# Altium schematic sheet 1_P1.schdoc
size 848 x 601 mm; Symbol: Drawing-Symbol_A4; Device: Drawing-Symbol_A4; Company: 嘉立创EDA; Version: V1.0; Page Size: A4; @Project Name: New Project; @Page Count: 1; @Update Date: 2025-11-15; @Create Date: 2025-05-18; @Schematic Name: Schematic1; @Page No: 1; @Page Name: P1; @Create Time: 04:48:49; @Update Time: 13:35:40; Width: 3304; Height: 2338; Region Start: 1; X Region Count: 6; Y Region Count: 4; Blade Width: 10; Title Block Position: 3; @Board Name: Board1
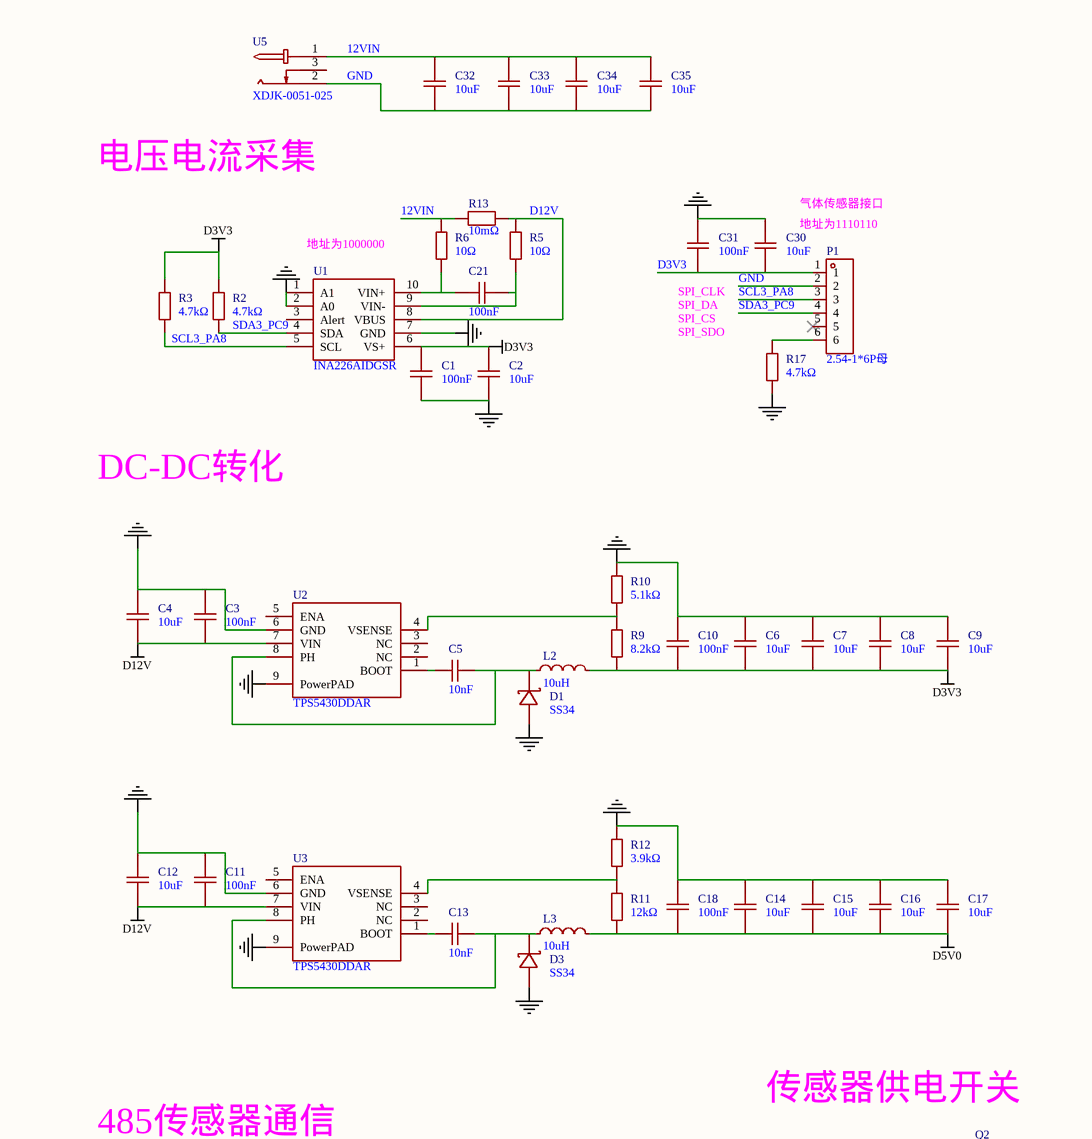
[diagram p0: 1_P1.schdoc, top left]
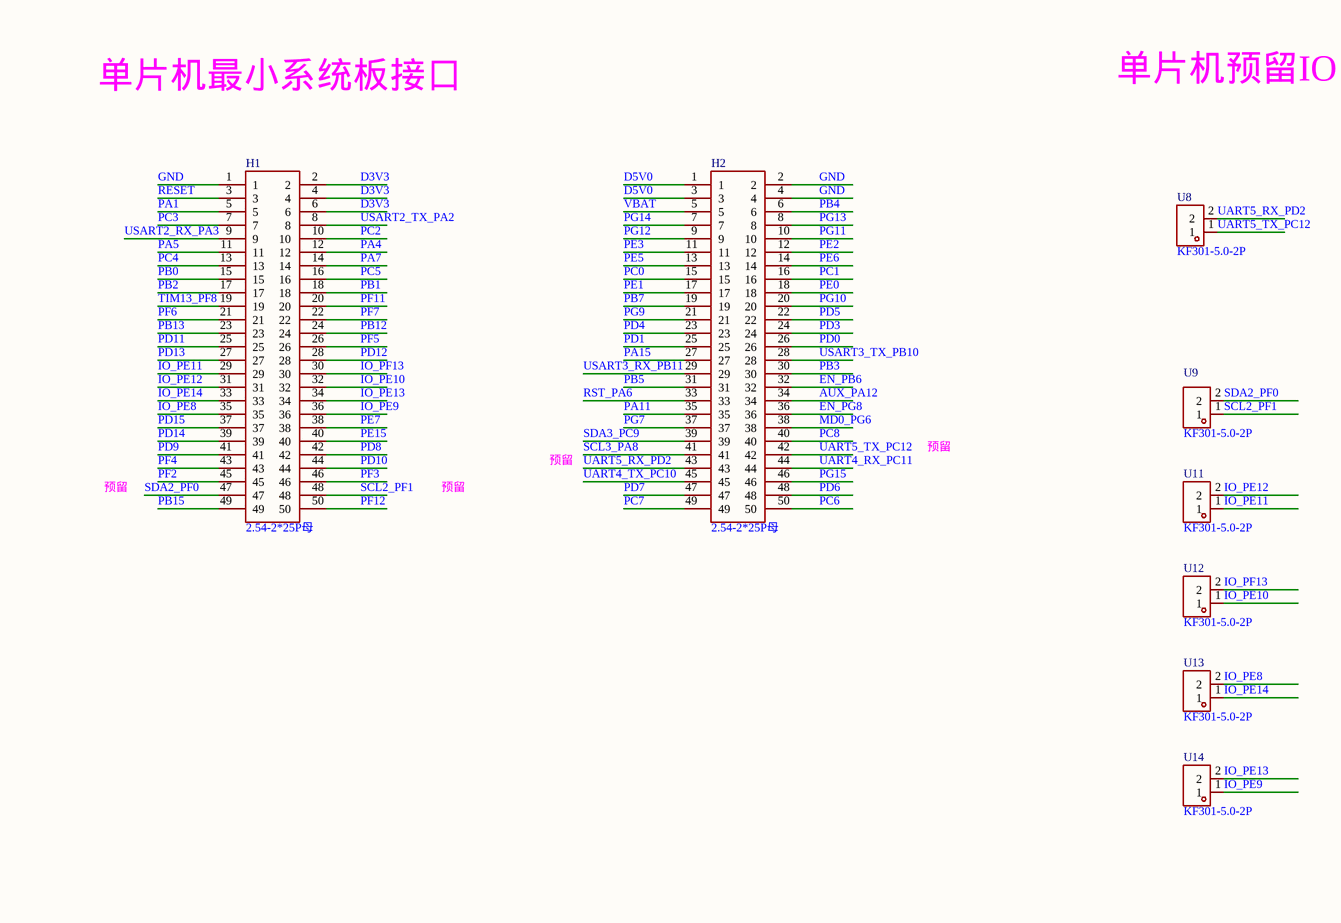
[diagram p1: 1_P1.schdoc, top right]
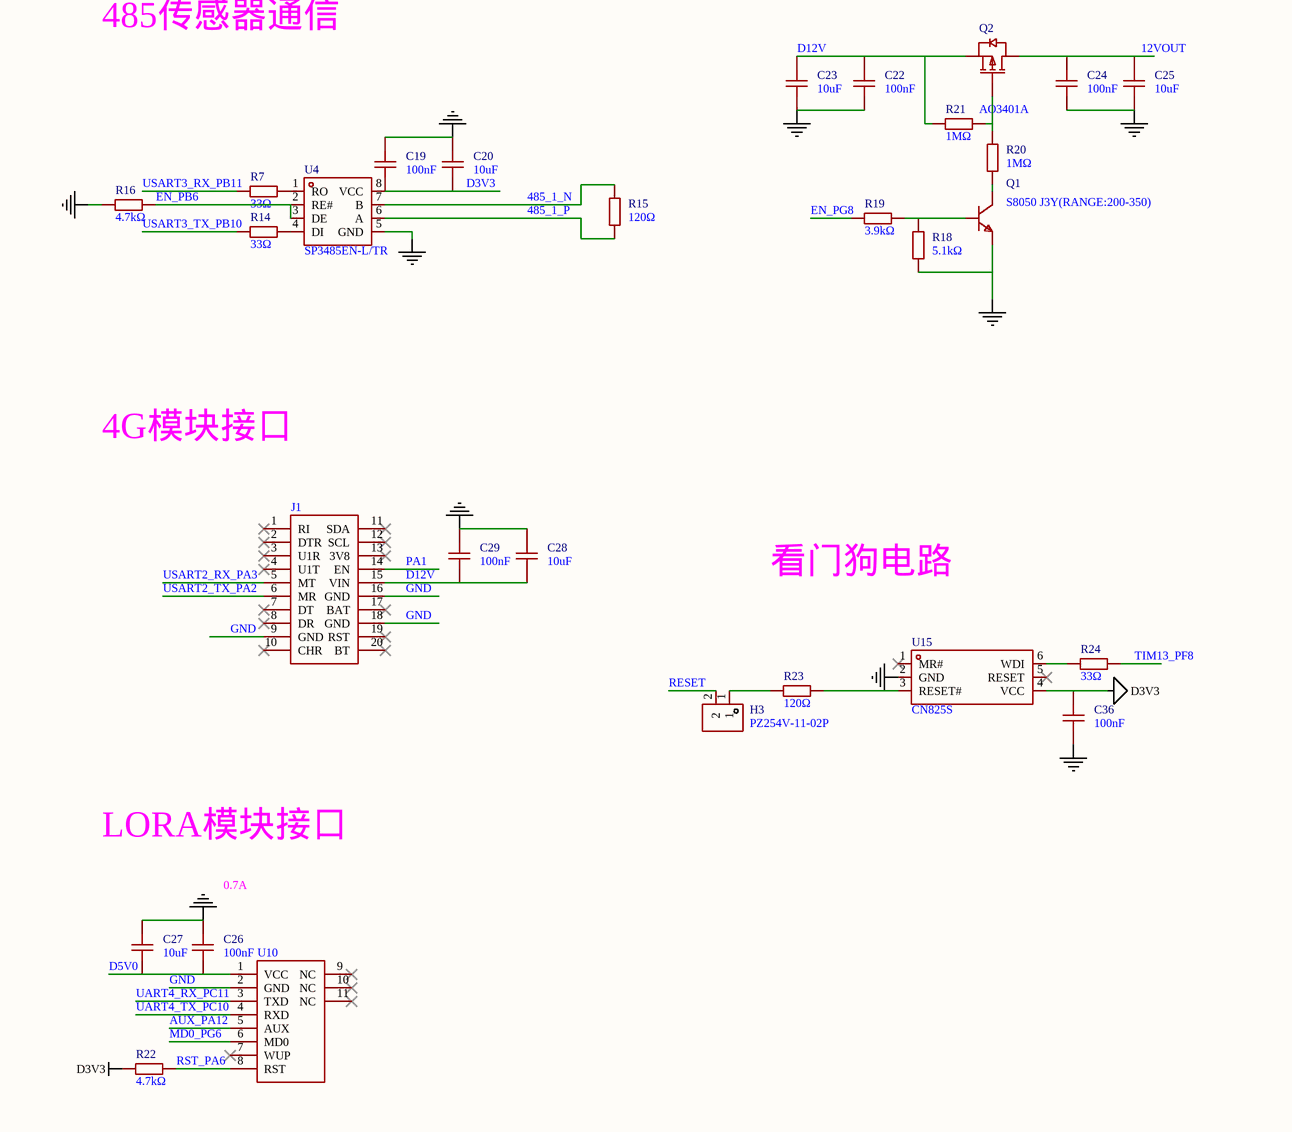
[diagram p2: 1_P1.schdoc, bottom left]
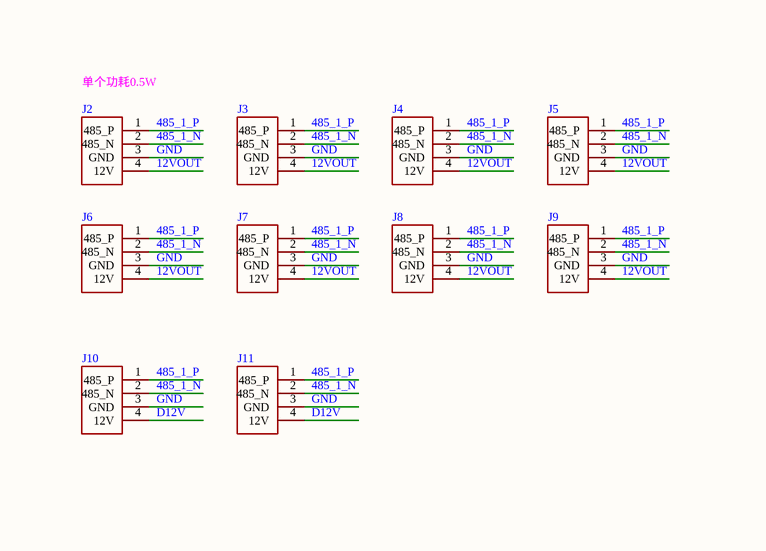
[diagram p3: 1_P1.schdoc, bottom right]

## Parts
C1  100nF  [C0603]
C2  10uF  [C0805]
C3  100nF  [C0603]
C4  10uF  [C0805]
C5  10nF  [C0603]
C6  10uF  [C0805]
C7  10uF  [C0805]
C8  10uF  [C0805]
C9  10uF  [C0805]
C10  100nF  [C0603]
C11  100nF  [C0603]
C12  10uF  [C0805]
C13  10nF  [C0603]
C14  10uF  [C0805]
C15  10uF  [C0805]
C16  10uF  [C0805]
C17  10uF  [C0805]
C18  100nF  [C0603]
C19  100nF  [C0603]
C20  10uF  [C0805]
C21  100nF  [C0603]
C22  100nF  [C0603]
C23  10uF  [C0805]
C24  100nF  [C0603]
C25  10uF  [C0805]
C26  100nF  [C0603]
C27  10uF  [C0805]
C28  10uF  [C0805]
C29  100nF  [C0603]
C30  10uF  [C0805]
C31  100nF  [C0603]
C32  10uF  [C0805]
C33  10uF  [C0805]
C34  10uF  [C0805]
C35  10uF  [C0805]
C36  100nF  [C0603]
D1  SS34  [SMA_L4.3-W2.6-LS5.2-RD]
D3  SS34  [SMA_L4.3-W2.6-LS5.2-RD]
H1  2.54-2*25P母  [HDR-TH_50P-P2.54-V-F-R2-C25-S2.54-1]
H2  2.54-2*25P母  [HDR-TH_50P-P2.54-V-F-R2-C25-S2.54-1]
H3  PZ254V-11-02P  [HDR-TH_2P-P2.54-V-M]
J1  (no value)  [HDR-TH_20P-P2.54-V-M-R2-C10-S2.54_HIF3H-20P-2.54W]
J2  (no value)  [CONN-TH_4P-P5.00_KF301-5.0-4P]
J3  (no value)  [CONN-TH_4P-P5.00_KF301-5.0-4P]
J4  (no value)  [CONN-TH_4P-P5.00_KF301-5.0-4P]
J5  (no value)  [CONN-TH_4P-P5.00_KF301-5.0-4P]
J6  (no value)  [CONN-TH_4P-P5.00_KF301-5.0-4P]
J7  (no value)  [CONN-TH_4P-P5.00_KF301-5.0-4P]
J8  (no value)  [CONN-TH_4P-P5.00_KF301-5.0-4P]
J9  (no value)  [CONN-TH_4P-P5.00_KF301-5.0-4P]
J10  (no value)  [CONN-TH_4P-P5.00_KF301-5.0-4P]
J11  (no value)  [CONN-TH_4P-P5.00_KF301-5.0-4P]
L2  10uH  [IND-SMD_L7.1-W6.6]
L3  10uH  [IND-SMD_L7.1-W6.6]
P1  2.54-1*6P母  [HDR-TH_6P-P2.54-V-F]
Q1  S8050 J3Y(RANGE:200-350)  [SOT-23-3_L3.0-W1.7-P0.95-LS2.9-BR]
Q2  AO3401A  [SOT-23_L2.9-W1.3-P1.90-LS2.4-BR]
R2  4.7kΩ  [R0603]
R3  4.7kΩ  [R0603]
R5  10Ω  [R0603]
R6  10Ω  [R0603]
R7  33Ω  [R0603]
R9  8.2kΩ  [R0603]
R10  5.1kΩ  [R0603]
R11  12kΩ  [R0603]
R12  3.9kΩ  [R0603]
R13  10mΩ  [R2512]
R14  33Ω  [R0603]
R15  120Ω  [R0603]
R16  4.7kΩ  [R0603]
R17  4.7kΩ  [R0603]
R18  5.1kΩ  [R0603]
R19  3.9kΩ  [R0603]
R20  1MΩ  [R0603]
R21  1MΩ  [R0603]
R22  4.7kΩ  [R0603]
R23  120Ω  [R0603]
R24  33Ω  [R0603]
U1  INA226AIDGSR  [MSOP-10_L3.0-W3.0-P0.50-LS5.0-BL]
U2  TPS5430DDAR  [ESOP-8_L4.9-W3.9-P1.27-LS6.0-TL-EP]
U3  TPS5430DDAR  [ESOP-8_L4.9-W3.9-P1.27-LS6.0-TL-EP]
U4  SP3485EN-L/TR  [SOIC-8_L5.0-W4.0-P1.27-LS6.0-BL]
U5  XDJK-0051-025  [DC-IN-TH_XDJK-0051-025]
U8  KF301-5.0-2P  [CONN-TH_P5.00_KF301-5.0-2P]
U9  KF301-5.0-2P  [CONN-TH_P5.00_KF301-5.0-2P]
U10  (no value)  [LORA]
U11  KF301-5.0-2P  [CONN-TH_P5.00_KF301-5.0-2P]
U12  KF301-5.0-2P  [CONN-TH_P5.00_KF301-5.0-2P]
U13  KF301-5.0-2P  [CONN-TH_P5.00_KF301-5.0-2P]
U14  KF301-5.0-2P  [CONN-TH_P5.00_KF301-5.0-2P]
U15  CN825S  [SOT-23-6_L2.9-W1.6-P0.95-LS2.8-BL]

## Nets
D3V3: C1.2 C2.2 C6.1 C7.1 C8.1 C9.1 C10.2 C19.2 C20.2 C30.2 C31.2 C36.2 H1.2 H1.4 H1.6 L2.2 P1.1 R2.2 R3.2 R9.1 R22.2 U1.6(VS+) U4.8(VCC) U15.4(VCC)
D5V0: C14.1 C15.1 C16.1 C17.1 C18.2 C26.2 C27.2 H2.1 H2.3 L3.2 R11.1 U10.1(VCC)
D12V: C3.2 C4.2 C11.2 C12.2 C22.1 C23.1 C28.2 C29.2 J1.15(VIN) J10.4(12V) J11.4(12V) Q2.2(S) R5.2 R13.2 R21.2 U1.8(VBUS) U2.7(VIN) U3.7(VIN)
GND: C1.1 C2.1 C3.1 C4.1 C6.2 C7.2 C8.2 C9.2 C10.1 C11.1 C12.1 C14.2 C15.2 C16.2 C17.2 C18.1 C19.1 C20.1 C22.2 C23.2 C24.2 C25.2 C26.1 C27.1 C28.1 C29.1 C30.1 C31.1 C32.2 C33.2 C34.2 C35.2 C36.1 D1.2(A) D3.2(A) H1.1 H2.2 H2.4 J1.9(GND) J1.16(GND) J1.18(GND) J2.3(GND) J3.3(GND) J4.3(GND) J5.3(GND) J6.3(GND) J7.3(GND) J8.3(GND) J9.3(GND) J10.3(GND) J11.3(GND) P1.2 Q1.2(E) R10.2 R12.2 R16.1 R17.1 R18.1 U1.1(A1) U1.2(A0) U1.7(GND) U2.6(GND) U2.9(PowerPAD) U3.6(GND) U3.9(PowerPAD) U4.5(GND) U5.2 U10.2(GND) U15.2(GND)
12VIN: C32.1 C33.1 C34.1 C35.1 R6.2 R13.1 U5.1
12VOUT: C24.1 C25.1 J2.4(12V) J3.4(12V) J4.4(12V) J5.4(12V) J6.4(12V) J7.4(12V) J8.4(12V) J9.4(12V) Q2.3(D)
485_1_N: J2.2(485_N) J3.2(485_N) J4.2(485_N) J5.2(485_N) J6.2(485_N) J7.2(485_N) J8.2(485_N) J9.2(485_N) J10.2(485_N) J11.2(485_N) R15.2 U4.7(B)
485_1_P: J2.1(485_P) J3.1(485_P) J4.1(485_P) J5.1(485_P) J6.1(485_P) J7.1(485_P) J8.1(485_P) J9.1(485_P) J10.1(485_P) J11.1(485_P) R15.1 U4.6(A)
AUX_PA12: H2.34 U10.5(AUX)
EN_PB6: H2.32 R16.2 U4.2(RE#) U4.3(DE)
EN_PG8: H2.36 R19.2
IO_PE8: H1.35 U13.2
IO_PE9: H1.36 U14.1
IO_PE10: H1.32 U12.1
IO_PE11: H1.29 U11.1
IO_PE12: H1.31 U11.2
IO_PE13: H1.34 U14.2
IO_PE14: H1.33 U13.1
IO_PF13: H1.30 U12.2
MD0_PG6: H2.38 U10.6(MD0)
PA1: H1.5 J1.14(EN)
PA4: H1.12
PA5: H1.11
PA7: H1.14
PA11: H2.35
PA15: H2.27
PB0: H1.15
PB1: H1.18
PB2: H1.17
PB3: H2.30
PB4: H2.6
PB5: H2.31
PB7: H2.19
PB12: H1.24
PB13: H1.23
PB15: H1.49
PC0: H2.15
PC1: H2.16
PC2: H1.10
PC3: H1.7
PC4: H1.13
PC5: H1.16
PC6: H2.50
PC7: H2.49
PC8: H2.40
PD0: H2.26
PD1: H2.25
PD3: H2.24
PD4: H2.23
PD5: H2.22
PD6: H2.48
PD7: H2.47
PD8: H1.42
PD9: H1.41
PD10: H1.44
PD11: H1.25
PD12: H1.28
PD13: H1.27
PD14: H1.39
PD15: H1.37
PE0: H2.18
PE1: H2.17
PE2: H2.12
PE3: H2.11
PE5: H2.13
PE6: H2.14
PE7: H1.38
PE15: H1.40
PF2: H1.45
PF3: H1.46
PF4: H1.43
PF5: H1.26
PF6: H1.21
PF7: H1.22
PF11: H1.20
PF12: H1.50
PG7: H2.37
PG9: H2.21
PG10: H2.20
PG11: H2.10
PG12: H2.9
PG13: H2.8
PG14: H2.7
PG15: H2.46
RESET: H1.3 H3.2
RST_PA6: H2.33 R22.1 U10.8(RST)
SCL2_PF1: H1.48 U9.1
SCL3_PA8: H2.41 P1.3 R3.1 U1.5(SCL)
SDA2_PF0: H1.47 U9.2
SDA3_PC9: H2.39 P1.4 R2.1 U1.4(SDA)
TIM13_PF8: H1.19 R24.2
UART4_RX_PC11: H2.44 U10.3(TXD)
UART4_TX_PC10: H2.45 U10.4(RXD)
UART5_RX_PD2: H2.43 U8.2
UART5_TX_PC12: H2.42 U8.1
USART2_RX_PA3: H1.9 J1.5(MT)
USART2_TX_PA2: H1.8 J1.6(MR)
USART3_RX_PB11: H2.29 R7.1
USART3_TX_PB10: H2.28 R14.1
VBAT: H2.5
NetC5_1: C5.1 D1.1(K) L2.1 U2.8(PH)
NetC5_2: C5.2 U2.1(BOOT)
NetC13_1: C13.1 D3.1(K) L3.1 U3.8(PH)
NetC13_2: C13.2 U3.1(BOOT)
NetC21_1: C21.1 R5.1 U1.9(VIN-)
NetC21_2: C21.2 R6.1 U1.10(VIN+)
NetH3_1: H3.1 R23.2
NetP1_6: P1.6 R17.2
NetQ1_1: Q1.1(B) R18.2 R19.1
NetQ1_3: Q1.3(C) R20.1
NetQ2_1: Q2.1(G) R20.2 R21.1
NetR7_2: R7.2 U4.1(RO)
NetR9_2: R9.2 R10.1 U2.4(VSENSE)
NetR11_2: R11.2 R12.1 U3.4(VSENSE)
NetR14_2: R14.2 U4.4(DI)
NetR23_1: R23.1 U15.3(RESET#)
NetR24_1: R24.1 U15.6(WDI)

Not connected (* = marked no-connect by the designer): J1 1(RI)* 2(DTR)* 3(U1R)* 4(U1T)* 7(DT)* 8(DR)* 10(CHR)* 11(SDA)* 12(SCL)* 13(3V8)* 17(BAT)* 19(RST)* 20(BT)*; P1 5*; U1 3(Alert); U2 2(NC) 3(NC) 5(ENA); U3 2(NC) 3(NC) 5(ENA); U5 3; U10 7(WUP)* 9(NC)* 10(NC)* 11(NC)*; U15 1(MR#)* 5(RESET)*

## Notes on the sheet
- 单片机最小系统板接口
- 单片机预留IO
- 电压电流采集
- 气体传感器接口
- 地址为1110110
- (near U1) 地址为1000000
- (near C31) SPI_CLK
- SPI_CS
- (near C31) SPI_DA
- SPI_SDO
- DC-DC转化
- 预留
- 传感器供电开关
- 485传感器通信
- (near J2) 单个功耗0.5W
- 4G模块接口
- 看门狗电路
- LORA模块接口
- (near C26) 0.7A

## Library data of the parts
C1 C3 C10 C11 C18 C19 C21 C22 C24 C26 C29 C31 C36 = CC0603KRX7R9BB104: Manufacturer: YAGEO(国巨); Add into BOM: yes; Tolerance: ±10%; Voltage Rated: 50V; Temperature Coefficient: X7R
C2 C4 C6-C9 C12 C14-C17 C20 C23 C25 C27 C28 C30 C32-C35 = CL21A106KAYNNNE_C15850: Manufacturer: SAMSUNG(三星); Add into BOM: yes; Tolerance: ±10%; Voltage Rated: 25V; Temperature Coefficient: X5R
C5 C13 = 0603B103K500NT: Manufacturer: FH(风华); Add into BOM: yes; Tolerance: ±10%; Voltage Rating: 50V; Temperature Coefficient: X7R
D1 D3 = SS34_C8678: Manufacturer: MDD(辰达半导体); Add into BOM: yes; Diode Configuration: 独立式; Forward Voltage (Vf@If): 550mV@3A; Reverse Voltage (Vr): 40V; Rectified Current: 3A; Reverse Leakage Current (Ir): 500uA@40V
H1 H2 = 2.54-2*25P母: Manufacturer: BOOMELE(博穆精密); Symbol: 2.54mm 2*25P female header; Add into BOM: yes; Holes Structure: 2x25P; Pitch: 2.54mm; Number of Holes: 50P
H3 = PZ254V-11-02P: Manufacturer: XFCN(兴飞); Add into BOM: yes; Pin Structure: 1x2P; Pitch: 2.54mm; Circluar Pins/Square Pins: 方针
J1 = EC800K核心板: Add into BOM: yes
J2-J11 = 传感器端子: Add into BOM: yes
L2 L3 = MWSA0603S-100MT: Manufacturer: Sunlord(顺络); Symbol: MWSA0603-100MT; Add into BOM: yes; Tolerance: ±20%; Rated Current: 4.5A; Current - Saturation(Isat): 5.5A; DC Resistance(DCR): 67mΩ
P1 = 2.54-1*6P母: Manufacturer: BOOMELE(博穆精密); Symbol: Header-Female-2.54_1x6; Add into BOM: yes; Holes Structure: 1x6P; Pitch: 2.54mm; Number of Holes: 6P
Q1 = S8050 J3Y(RANGE:200-350): Manufacturer: CJ(江苏长电/长晶); Symbol: S8050_C2146; Add into BOM: yes; type: NPN; Current - Collector(Ic): 500mA; Collector - Emitter Voltage VCEO: 25V; Pd - Power Dissipation: 300mW; DC Current Gain: 200@500mA,1V; Transition frequency(fT): 150MHz; Current - Collector Cutoff: 100nA; Vce Saturation(VCE(sat)): 600mV
Q2 = AO3401A_C15127: Manufacturer: AOS; Add into BOM: yes; Type: 1个P沟道; Drain Source Voltage (Vdss): 30V; Continuous Drain Current (Id): 4A; Drain Source On Resistance (RDS(on)@Vgs,Id): 44mΩ@10V,4.3A; Power Dissipation (Pd): 1.4W; Gate Threshold Voltage (Vgs(th)@Id): 1.3V@250uA; Total Gate Charge (Qg@Vgs): 12.2nC@4.5V; Input Capacitance (Ciss@Vds): 1.2nF@15V
R2 R3 R16 R17 R22 = 0603WAF4701T5E: Manufacturer: UNI-ROYAL(厚声); Add into BOM: yes; Tolerance: ±1%; Power(Watts): 100mW; Overload Voltage (Max): 75V; Temperature Coefficient: ±100ppm/℃
R5 R6 = 0603WAF100JT5E: Manufacturer: UNI-ROYAL(厚声); Add into BOM: yes; Tolerance: ±1%; Power(Watts): 100mW; Overload Voltage (Max): 75V; Temperature Coefficient: ±400ppm/℃
R7 R14 R24 = 0603WAF330JT5E: Manufacturer: UNI-ROYAL(厚声); Add into BOM: yes; Tolerance: ±1%; Power(Watts): 100mW; Overload Voltage (Max): 75V; Temperature Coefficient: ±100ppm/℃
R9 = 0603WAF8201T5E: Manufacturer: UNI-ROYAL(厚声); Add into BOM: yes; Tolerance: ±1%; Power(Watts): 100mW; Overload Voltage (Max): 75V; Temperature Coefficient: ±100ppm/℃
R10 R18 = 0603WAF5101T5E: Manufacturer: UNI-ROYAL(厚声); Add into BOM: yes; Tolerance: ±1%; Power(Watts): 100mW; Overload Voltage (Max): 75V; Temperature Coefficient: ±100ppm/℃
R11 = 0603WAF1202T5E: Manufacturer: UNI-ROYAL(厚声); Add into BOM: yes; Tolerance: ±1%; Power(Watts): 100mW; Overload Voltage (Max): 75V; Temperature Coefficient: ±100ppm/℃
R12 R19 = 0603WAF3901T5E: Manufacturer: UNI-ROYAL(厚声); Add into BOM: yes; Tolerance: ±1%; Power(Watts): 100mW; Overload Voltage (Max): 75V; Temperature Coefficient: ±100ppm/℃
R13 = JER2512F3R010: Manufacturer: 捷而瑞; Add into BOM: yes; Tolerance: ±1%; Power(Watts): 3W; Temperature Coefficient: ±50ppm/℃
R15 R23 = 0603WAF1200T5E: Manufacturer: UNI-ROYAL(厚声); Add into BOM: yes; Tolerance: ±1%; Power(Watts): 100mW; Overload Voltage (Max): 75V; Temperature Coefficient: ±100ppm/℃
R20 R21 = 0603WAF1004T5E: Manufacturer: UNI-ROYAL(厚声); Add into BOM: yes; Tolerance: ±1%; Power(Watts): 100mW; Overload Voltage (Max): 75V; Temperature Coefficient: ±100ppm/℃
U1 = INA226AIDGSR: Manufacturer: TI(德州仪器); Add into BOM: yes; Vcm - Common Mode Voltage: 300mV~40V; Voltage - Supply: 2.7V~5.5V
U2 U3 = TPS5430DDAR: Manufacturer: TI(德州仪器); Add into BOM: yes; Function: 降压型; Output Type: 可调; Input Voltage: 5.5V~36V; Output Voltage: 1.221V~32.04V; Output Current: 3A; Switching Frequency: 500kHz; Synchronous Rectification: 否; Number of Outputs: 1; Topology: 降压式; Switch tube (built-in/external): 内置
U4 = SP3485EN-L/TR: Manufacturer: MaxLinear(迈凌); Add into BOM: yes; Types: 收发器; Number of Driver: 1; Supply Voltage: 3.3V; Data Rate: 10Mbps
U5 = XDJK-0051-025: Manufacturer: LX(连欣科技); Add into BOM: yes; Connector Type: DC电源插座; Inside Contact Diameter: 2.1mm; Outside Contact Diameter: 6.3mm; Current Rating (Max): 3A; Voltage Rating (Max): 500V; Soldering Temperature(Max): 265℃
U8 U9 U11-U14 = KF301-5.0-2P: Manufacturer: KEFA(科发); Add into BOM: yes; Structure: 1x2P; Pitch: 5mm; Current Rating (Max): 17A; Voltage Rating (Max): 250V; Wire Gauge - AWG: 14~22; Wire Gauge - mm2: 1.5; Number of PINs Per Row: 2
U10 = LORA模块: Add into BOM: yes
U15 = CN825S: Manufacturer: CONSONANCE(上海如韵); Add into BOM: yes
